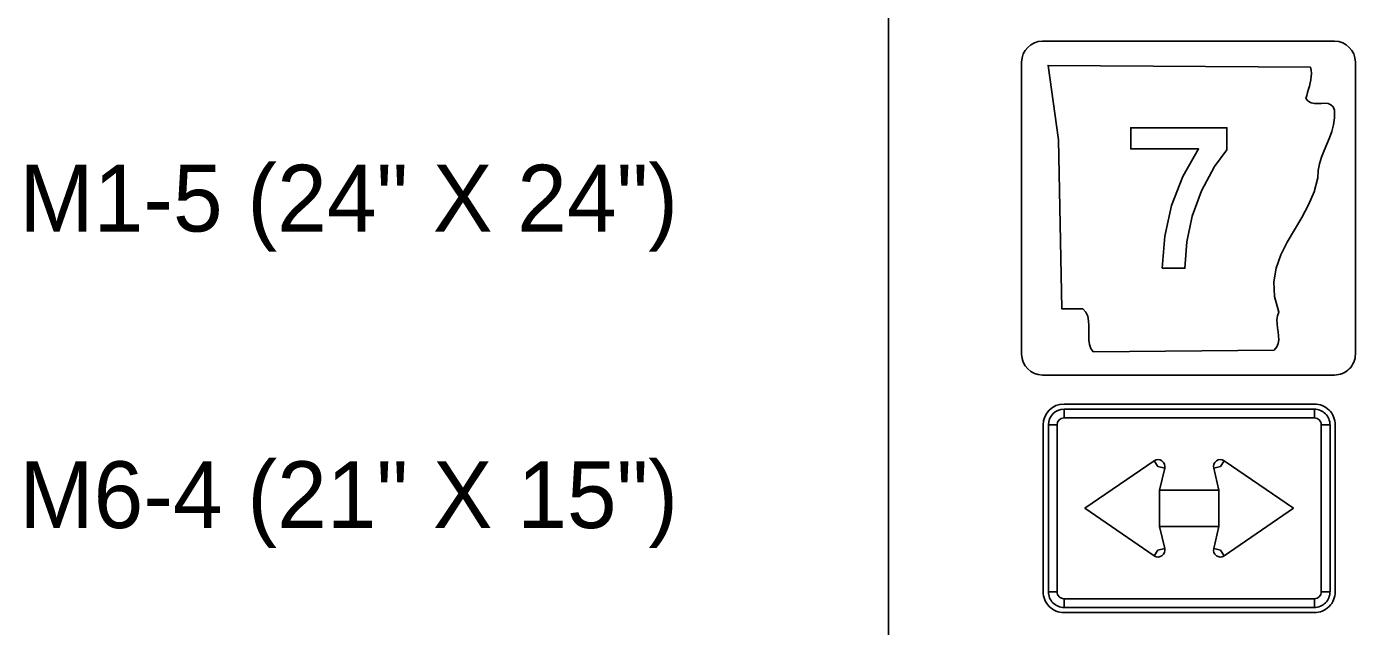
# Model space of a CAD drawing. Extents: x 1001568 to 1002149, y 1840825 to 1841423.
# Drawn here: x 1001930.48 to 1001938.45, y 1841183.77 to 1841187.36 of the extents above; entities that cross this region are included whole.
import ezdxf

# ---------------------------------------------------------------- set-up
doc = ezdxf.new("R2010")
doc.units = 0
for name, color, linetype in [('40', 7, 'Continuous'), ('R_No Plot', 7, 'Continuous'), ('SIGNS', 7, 'Continuous')]:
    doc.layers.add(name, color=color, linetype=linetype)

msp = doc.modelspace()

# ---------------------------------------------------------------- linework, layer by layer
at = {"layer": 'R_No Plot'}
msp.add_line((1001935.6501, 1841210.6666), (1001935.6501, 1841148.1274), dxfattribs=at)
at = {"layer": 'SIGNS'}
for p, q in [((1001938.3226, 1841187.2755), (1001936.5726, 1841187.2755)), ((1001936.4476, 1841187.1505), (1001936.4476, 1841185.4005)), ((1001938.4476, 1841185.4005), (1001938.4476, 1841187.1505)), ((1001936.4476, 1841185.4005), (1001936.4476, 1841185.4005)), ((1001936.5726, 1841185.2755), (1001938.3226, 1841185.2755)), ((1001938.2015, 1841185.1018), (1001936.7015, 1841185.1018)), ((1001936.7015, 1841185.0185), (1001936.7015, 1841185.0706)), ((1001938.2015, 1841185.0706), (1001938.2015, 1841185.0185)), ((1001936.5765, 1841184.9768), (1001936.5765, 1841183.9768)), ((1001936.6078, 1841184.9768), (1001936.6599, 1841184.9768)), ((1001938.2432, 1841184.9768), (1001938.2953, 1841184.9768)), ((1001938.3265, 1841183.9768), (1001938.3265, 1841184.9768)), ((1001937.2418, 1841184.762), (1001937.264, 1841184.7268)), ((1001937.264, 1841184.7268), (1001937.3046, 1841184.7175)), ((1001937.5984, 1841184.7175), (1001937.639, 1841184.7268)), ((1001937.639, 1841184.7268), (1001937.6613, 1841184.762)), ((1001937.3046, 1841184.2361), (1001937.264, 1841184.2268)), ((1001937.639, 1841184.2268), (1001937.5984, 1841184.2361)), ((1001937.264, 1841184.2268), (1001937.2418, 1841184.1916)), ((1001937.6613, 1841184.1916), (1001937.639, 1841184.2268)), ((1001936.6599, 1841183.9768), (1001936.6078, 1841183.9768)), ((1001936.7015, 1841183.8831), (1001936.7015, 1841183.9351)), ((1001938.2015, 1841183.9351), (1001938.2015, 1841183.8831)), ((1001938.2953, 1841183.9768), (1001938.2432, 1841183.9768)), ((1001936.7015, 1841183.8518), (1001938.2015, 1841183.8518))]:
    msp.add_line(p, q, dxfattribs=at)
for points in [[(1001936.5726, 1841187.2755), (1001936.5726, 1841187.2755)], [(1001938.3226, 1841187.2755), (1001938.3226, 1841187.2755)], [(1001936.4476, 1841187.1505), (1001936.4476, 1841187.1505)], [(1001936.5726, 1841185.2755), (1001936.5726, 1841185.2755)], [(1001938.3226, 1841185.2755), (1001938.3226, 1841185.2755)]]:
    msp.add_lwpolyline(points, dxfattribs=at)
for points in [[(1001938.1775, 1841187.1211), (1001938.1822, 1841187.1021), (1001938.1839, 1841187.0826), (1001938.1832, 1841187.0635), (1001938.1809, 1841187.0444), (1001938.1769, 1841187.0253), (1001938.1722, 1841187.0066), (1001938.1665, 1841186.9875), (1001938.1608, 1841186.9692), (1001938.1555, 1841186.9508), (1001938.1505, 1841186.9324), (1001938.1645, 1841186.9163), (1001938.1819, 1841186.9071), (1001938.2016, 1841186.9031), (1001938.223, 1841186.9027), (1001938.2443, 1841186.9034), (1001938.2651, 1841186.9038), (1001938.2841, 1841186.9016), (1001938.3008, 1841186.8954), (1001938.3139, 1841186.8832), (1001938.3219, 1841186.8631), (1001938.3225, 1841186.8175), (1001938.3169, 1841186.7749), (1001938.3062, 1841186.7346), (1001938.2918, 1841186.696), (1001938.2761, 1841186.6578), (1001938.26, 1841186.62), (1001938.245, 1841186.5815), (1001938.233, 1841186.5418), (1001938.2247, 1841186.5003), (1001938.2227, 1841186.4563), (1001938.2006, 1841186.3741), (1001938.1668, 1841186.2959), (1001938.126, 1841186.2202), (1001938.0819, 1841186.1453), (1001938.0388, 1841186.0708), (1001938.0011, 1841185.9948), (1001937.973, 1841185.9163), (1001937.9586, 1841185.8337), (1001937.962, 1841185.7463), (1001937.9877, 1841185.6527), (1001937.98, 1841185.6295), (1001937.9774, 1841185.6057), (1001937.978, 1841185.5818), (1001937.981, 1841185.5576), (1001937.9844, 1841185.5337), (1001937.987, 1841185.5102), (1001937.9877, 1841185.4871), (1001937.9844, 1841185.4654), (1001937.976, 1841185.4442), (1001937.9606, 1841185.4243), (1001936.8769, 1841185.4144), (1001936.8622, 1841185.4342), (1001936.8539, 1841185.4581), (1001936.8502, 1841185.4845), (1001936.8499, 1841185.5128), (1001936.8505, 1841185.5425), (1001936.8509, 1841185.5719), (1001936.8489, 1841185.6009), (1001936.8432, 1841185.6277), (1001936.8321, 1841185.6519), (1001936.8138, 1841185.6725), (1001936.6875, 1841185.6725), (1001936.6694, 1841186.6843), (1001936.6059, 1841187.131), (1001938.1775, 1841187.1211), (1001938.1775, 1841187.1211)], [(1001937.2901, 1841185.9151), (1001937.4261, 1841185.9151), (1001937.4369, 1841186.0734), (1001937.4701, 1841186.2281), (1001937.5257, 1841186.3782), (1001937.6033, 1841186.5244), (1001937.678, 1841186.6248), (1001937.678, 1841186.7568), (1001937.1009, 1841186.7568), (1001937.1009, 1841186.6307), (1001937.5075, 1841186.6307), (1001937.4137, 1841186.4657), (1001937.3464, 1841186.2915), (1001937.3051, 1841186.108)], [(1001938.2015, 1841185.0706), (1001936.7015, 1841185.0706), (1001936.7015, 1841185.0185), (1001938.2015, 1841185.0185), (1001938.2015, 1841185.0706), (1001938.2015, 1841185.0706)], [(1001936.6078, 1841184.9768), (1001936.6078, 1841183.9768), (1001936.6599, 1841183.9768), (1001936.6599, 1841184.9768), (1001936.6078, 1841184.9768), (1001936.6078, 1841184.9768)], [(1001938.2953, 1841183.9768), (1001938.2953, 1841184.9768), (1001938.2432, 1841184.9768), (1001938.2432, 1841183.9768), (1001938.2953, 1841183.9768), (1001938.2953, 1841183.9768)], [(1001936.8265, 1841184.4768), (1001937.2418, 1841184.1916), (1001937.264, 1841184.2268), (1001937.3046, 1841184.2361), (1001937.2745, 1841184.3674), (1001937.2745, 1841184.5862), (1001937.3046, 1841184.7175), (1001937.264, 1841184.7268), (1001937.2418, 1841184.762), (1001936.8265, 1841184.4768), (1001936.8265, 1841184.4768)], [(1001938.0765, 1841184.4768), (1001937.6613, 1841184.762), (1001937.639, 1841184.7268), (1001937.5984, 1841184.7175), (1001937.6286, 1841184.5862), (1001937.6286, 1841184.3674), (1001937.5984, 1841184.2361), (1001937.639, 1841184.2268), (1001937.6613, 1841184.1916), (1001938.0765, 1841184.4768), (1001938.0765, 1841184.4768)], [(1001937.6286, 1841184.3674), (1001937.6286, 1841184.5862), (1001937.2745, 1841184.5862), (1001937.2745, 1841184.3674), (1001937.6286, 1841184.3674), (1001937.6286, 1841184.3674)], [(1001936.7015, 1841183.8831), (1001938.2015, 1841183.8831), (1001938.2015, 1841183.9351), (1001936.7015, 1841183.9351), (1001936.7015, 1841183.8831), (1001936.7015, 1841183.8831)]]:
    msp.add_lwpolyline(points, close=True, dxfattribs=at)
for centre, radius, start, end in [((1001936.5726, 1841187.1505), 0.125, 90.00021, 179.99985), ((1001938.3226, 1841187.1505), 0.125, 360, 90), ((1001936.5726, 1841185.4005), 0.125, 180, 270), ((1001938.3226, 1841185.4005), 0.125, 270.00006, 0.00027), ((1001936.7015, 1841184.9768), 0.125, 90.00021, 179.99985), ((1001936.7015, 1841184.9768), 0.0937, 90.00021, 179.99985), ((1001938.2015, 1841184.9768), 0.125, 360, 90.00021), ((1001938.2015, 1841184.9768), 0.0937, 360, 90.00021), ((1001936.7015, 1841184.9768), 0.0417, 90.00021, 179.99985), ((1001938.2015, 1841184.9768), 0.0417, 360, 90.00021), ((1001937.264, 1841184.7268), 0.0417, 347.0497, 122.27576), ((1001937.639, 1841184.7268), 0.0417, 57.72435, 192.95041), ((1001937.264, 1841184.2268), 0.0417, 237.7242, 12.95026), ((1001937.639, 1841184.2268), 0.0417, 167.04986, 302.27592), ((1001936.7015, 1841183.9768), 0.125, 179.99985, 270.00006), ((1001936.7015, 1841183.9768), 0.0937, 179.99985, 270.00006), ((1001936.7015, 1841183.9768), 0.0417, 179.99985, 270.00006), ((1001938.2015, 1841183.9768), 0.125, 270.00006, 0.00027), ((1001938.2015, 1841183.9768), 0.0937, 270.00006, 0.00027), ((1001938.2015, 1841183.9768), 0.0417, 270.00006, 0.00027)]:
    msp.add_arc(centre, radius, start, end, dxfattribs=at)

# ---------------------------------------------------------------- texts
at = {"layer": '40'}
for s, p in [('M1-5 (24" X 24")', (1001930.4411, 1841186.1353)), ('M6-4 (21" X 15")', (1001930.4411, 1841184.3585))]:
    msp.add_text(s, height=0.4, rotation=0, dxfattribs=at).set_placement(p)

doc.saveas('drawing.dxf')
